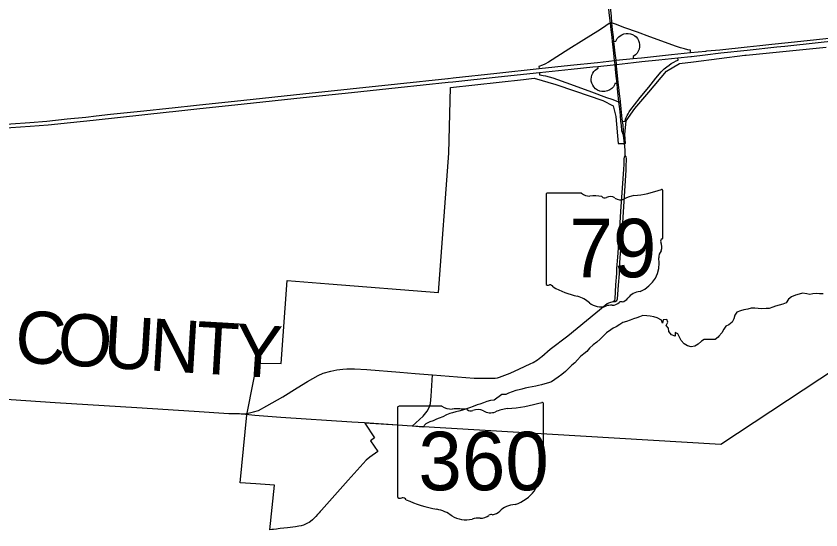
# Model space of a CAD drawing. Extents: x 1853412 to 2125412, y 78841 to 855418.
# Drawn here: x 1962525 to 1977959, y 699538 to 709388 of the extents above; entities that cross this region are included whole.
import ezdxf

# ---------------------------------------------------------------- set-up
doc = ezdxf.new("R2010")
doc.units = 0
for name, color, linetype in [('GM_X_Corporation', 7, 'Continuous'), ('GM_X_County', 7, 'Continuous'), ('GM_X_County_Text', 7, 'Continuous'), ('GM_X_Interstate_Location', 7, 'Continuous'), ('GM_X_Interstate_Route', 7, 'Continuous'), ('GM_X_State_Location', 7, 'Continuous'), ('GM_X_State_Route', 7, 'Continuous'), ('GM_X_State_Shield', 7, 'Continuous'), ('UT_P_Electric', 7, 'Continuous')]:
    doc.layers.add(name, color=color, linetype=linetype)

msp = doc.modelspace()

# ---------------------------------------------------------------- linework, layer by layer
at = {"layer": 'GM_X_Corporation'}
msp.add_lwpolyline([(1978000, 704064), (1977932, 704064), (1977876, 704068), (1977806, 704061), (1977746, 704053), (1977686, 704063), (1977606, 704079), (1977544, 704060), (1977474, 704038), (1977392, 704004), (1977336, 703962), (1977292, 703890), (1977228, 703867), (1977088, 703827), (1977034, 703809), (1976966, 703780), (1976908, 703782), (1976826, 703776), (1976757, 703780), (1976693, 703791), (1976623, 703789), (1976555, 703771), (1976483, 703759), (1976417, 703736), (1976345, 703712), (1976305, 703654), (1976291, 703586), (1976258, 703520), (1976190, 703470), (1976138, 703444), (1976098, 703386), (1976058, 703317), (1976004, 703251), (1975986, 703233), (1975928, 703191), (1975792, 703191), (1975722, 703186), (1975672, 703156), (1975606, 703100), (1975540, 703058), (1975470, 703049), (1975400, 703065), (1975336, 703103), (1975281, 703169), (1975245, 703234), (1975215, 703298), (1975161, 703324), (1975161, 703252), (1975093, 703278), (1975042, 703340), (1975034, 703403), (1974994, 703455), (1975026, 703519), (1975001, 703569), (1974935, 703565), (1974921, 703503), (1974903, 703559), (1974821, 703606), (1974755, 703624), (1974685, 703634), (1974618, 703640), (1974546, 703645), (1974480, 703621), (1974426, 703601), (1974364, 703583), (1974298, 703558), (1974228, 703532), (1974162, 703514), (1974100, 703474), (1974034, 703434), (1973978, 703405), (1973928, 703373), (1973850, 703319), (1973787, 703257), (1973723, 703197), (1973659, 703136), (1973591, 703084), (1973521, 703020), (1973467, 702956), (1973411, 702912), (1973347, 702862), (1973288, 702801), (1973238, 702739), (1973182, 702695), (1973126, 702639), (1973060, 702575), (1972992, 702517), (1972922, 702464), (1972858, 702424), (1972790, 702378), (1972736, 702360), (1972666, 702337), (1972598, 702321), (1972546, 702309), (1972494, 702295), (1972422, 702279), (1972352, 702268), (1972290, 702252), (1972226, 702238), (1972170, 702226), (1972106, 702211), (1972038, 702187), (1971968, 702161), (1971916, 702135), (1971840, 702133), (1971696, 702026), (1971622, 702018), (1971552, 702002), (1971486, 701977), (1971420, 701949), (1971366, 701933), (1971290, 701905), (1971222, 701880), (1971164, 701860), (1971084, 701836), (1971014, 701814), (1970960, 701803), (1970896, 701785), (1970842, 701769), (1970776, 701743), (1970708, 701705), (1970640, 701680), (1970588, 701658), (1970522, 701632), (1970456, 701612), (1970384, 701569), (1970327, 701510), (1970119, 701527), (1969837, 701546), (1969210, 701587), (1969396, 701302), (1969323, 701248), (1969459, 701039), (1969310, 700931), (1969239, 700878), (1968890, 700493), (1968381, 699919), (1968358, 699893), (1968335, 699867), (1968304, 699831), (1968273, 699796), (1968240, 699760), (1968208, 699730), (1968171, 699701), (1968143, 699682), (1968113, 699664), (1968074, 699646), (1968034, 699630), (1967989, 699616), (1967947, 699607), (1967882, 699598), (1967727, 699579), (1967588, 699562), (1967550, 699558), (1967519, 699554), (1967458, 699546), (1967426, 699543), (1967390, 699538), (1967478, 700396), (1967125, 700420), (1966820, 700440), (1966820, 700440), (1966949, 701742), (1967077, 702390), (1967145, 702736), (1967606, 702725), (1967720, 704321), (1968521, 704257), (1970628, 704088), (1970821, 706758), (1970854, 708016), (1972257, 708173), (1972461, 708196), (1972877, 708076), (1973233, 707955), (1973774, 707770), (1973978, 707667), (1974025, 707464), (1974071, 706947), (1974213, 706947), (1974198, 707115), (1974223, 707380), (1974390, 707615), (1974660, 707931), (1974999, 708334), (1975250, 708479), (1975518, 708513), (1976501, 708639), (1976528, 708641), (1978057, 708794)], dxfattribs=at)
at = {"layer": 'GM_X_County'}
msp.add_lwpolyline([(1991425, 702099), (1978895, 703062), (1976042, 701178), (1970119, 701527), (1969837, 701546), (1969206, 701588), (1968963, 701604), (1967601, 701695), (1967104, 701729), (1966807, 701761), (1966648, 701765), (1966605, 701765), (1965937, 701808), (1964838, 701880), (1963273, 701974), (1962141, 702051), (1961404, 702092), (1960067, 702149), (1959325, 702195), (1956245, 702403), (1956176, 702427), (1945541, 702974)], dxfattribs=at)
at = {"layer": 'GM_X_Interstate_Route'}
msp.add_line((1970807, 708193), (1970813, 708194), dxfattribs=at)
at = {"layer": 'GM_X_State_Route'}
msp.add_line((1974196, 706888), (1974170, 707104), dxfattribs=at)
for points in [[(1974208, 706714), (1974207, 706759), (1974204, 706817), (1974196, 706888)], [(1973975, 703918), (1974015, 703918), (1974048, 703933), (1974059, 703967), (1974078, 704230), (1974094, 704448), (1974098, 704538), (1974112, 704759), (1974145, 705203), (1974174, 705637), (1974221, 706435), (1974226, 706482), (1974226, 706542), (1974228, 706604), (1974228, 706652), (1974221, 706691), (1974208, 706714)], [(1973975, 703918), (1974005, 703941), (1974012, 703970), (1974027, 704238), (1974043, 704456), (1974047, 704546), (1974062, 704766), (1974095, 705210), (1974123, 705644), (1974179, 706454), (1974183, 706540), (1974186, 706597), (1974188, 706646), (1974191, 706690), (1974208, 706714)], [(1970512, 702511), (1971311, 702449), (1971712, 702444), (1971758, 702450), (1971793, 702463), (1971997, 702544), (1972181, 702626), (1972380, 702719), (1972439, 702749), (1972523, 702801), (1972585, 702847), (1972604, 702861), (1972768, 703001), (1973106, 703260), (1973820, 703849), (1973863, 703879), (1973908, 703896), (1973975, 703918)], [(1966939, 701770), (1966950, 701771), (1967075, 701800), (1967171, 701829), (1967336, 701916), (1967639, 702088), (1967915, 702263), (1968110, 702386), (1968315, 702499), (1968413, 702541), (1968561, 702582), (1968677, 702608), (1968789, 702621), (1968870, 702628), (1969012, 702626), (1969251, 702614), (1969884, 702562), (1970180, 702537), (1970512, 702511)], [(1970120, 701524), (1970330, 701719), (1970409, 701812), (1970449, 701887), (1970474, 701962), (1970487, 702103), (1970512, 702511)], [(1966839, 701761), (1966880, 701764), (1966939, 701770)]]:
    msp.add_lwpolyline(points, dxfattribs=at)
at = {"layer": 'GM_X_State_Shield'}
for p, q in [((1972688, 705962), (1972688, 704261)), ((1973367, 705991), (1972710, 705991)), ((1974930, 705143), (1974930, 706033)), ((1974930, 705144), (1974930, 705143)), ((1972642, 701061), (1972642, 701951)), ((1969841, 701880), (1969841, 700178)), ((1970689, 701909), (1969868, 701909)), ((1972642, 701061), (1972642, 701061))]:
    msp.add_line(p, q, dxfattribs=at)
for centre, radius, start, end in [((1972714, 705966), 26, 98.1301, 188.1301), ((1973523, 706189), 252, 231.6195, 271.1119), ((1974131, 708311), 2377, 275.8445, 288.9065), ((1974905, 706037), 25, 351.8621, 97.738), ((1973607, 705036), 904, 80.4867, 94.9883), ((1973812, 705974), 72.7, 219.7921, 297.1024), ((1973919, 705778), 151, 54.4667, 119.1411), ((1974114, 706047), 182, 233.8562, 294.8282), ((1974435, 705472), 478, 97.3462, 120.7689), ((1974924, 705078), 38.6, 107.944, 210.337), ((1974678, 704966), 232, 340.033, 23.6496), ((1974903, 705140), 26.7, 289.6038, 7.7341), ((1975019, 704771), 169, 136.8065, 186.9296), ((1974265, 704658), 595, 292.3089, 8.9858), ((1972714, 704257), 26.2, 171.9584, 258.3066), ((1972718, 704431), 200, 267.339, 280.6039), ((1972759, 704163), 72.1, 29.7484, 93.2717), ((1973669, 705691), 1716, 240.4129, 257.1985), ((1974515, 703783), 326, 94.4031, 142.5768), ((1973158, 703496), 537, 47.1842, 75.836), ((1974103, 704096), 192, 282.8732, 323.2771), ((1973738, 704154), 341, 230.7004, 286.2918), ((1973935, 703566), 280, 85.6951, 111.2099), ((1973960, 704027), 182, 268.777, 315.5493), ((1974124, 703862), 51.1, 65.7517, 132.6484)]:
    msp.add_arc(centre, radius, start, end, dxfattribs=at)
for centre, major_axis, start_param, end_param in [((1971644, 704228), (2971, 0), 4.814394, 5.042369), ((1972611, 701955), (31.2, 0), 6.141152, 7.989035), ((1969873, 701883), (32.5, 0), 1.712693, 3.28349), ((1970884, 702106), (315, 0), 4.042523, 4.731795), ((1970988, 700954), (1130, 0), 1.404758, 1.657858), ((1971245, 701892), (90.8, 0), 3.836095, 5.185415), ((1971378, 701695), (189, 0), 0.950623, 2.079405), ((1971622, 701965), (227, 0), 4.081561, 5.145723), ((1972023, 701389), (598, 0), 1.699011, 2.107814), ((1972635, 700996), (48.3, 0), 1.883978, 3.671073), ((1972609, 701058), (33.4, 0), 5.05454, 6.418171), ((1972328, 700883), (290, 0), 5.934695, 6.695948), ((1972754, 700689), (211, 0), 2.387724, 3.262537), ((1971811, 700575), (743, 0), 5.101752, 6.440018), ((1969873, 700175), (32.7, 0), 3.00124, 4.508301), ((1969878, 700349), (250, 0), 4.665946, 4.897461), ((1969929, 700080), (90.1, 0), 0.519207, 1.627899), ((1971067, 701609), (2146, 0), 4.195997, 4.488961), ((1970427, 699414), (671, 0), 0.823519, 1.323587), ((1972124, 699701), (407, 0), 1.647645, 2.488434), ((1971153, 700072), (426, 0), 4.026481, 4.996735), ((1971430, 699944), (227, 0), 4.691044, 5.507374), ((1971636, 699780), (63.9, 0), 1.147584, 2.315152), ((1971608, 700014), (240, 0), 4.937069, 5.64225), ((1971399, 699484), (350, 0), 1.495662, 1.94098)]:
    msp.add_ellipse(centre, major_axis=major_axis, ratio=0.8, start_param=start_param, end_param=end_param, dxfattribs=at)
at = {"layer": 'UT_P_Electric'}
for p, q in [((1975477, 708616), (1975739, 708648)), ((1974156, 707369), (1974143, 707475))]:
    msp.add_line(p, q, dxfattribs=at)
for points in [[(1973924, 709254), (1973907, 709402), (1973894, 709523), (1973880, 709660)], [(1974042, 708427), (1974039, 708460), (1974030, 708542), (1974015, 708680), (1973996, 708852), (1973990, 708899), (1973981, 708987), (1973965, 709125), (1973952, 709257), (1973940, 709387), (1973928, 709501), (1973922, 709555)], [(1973952, 709257), (1973924, 709254), (1973897, 709244), (1973837, 709202), (1973809, 709181), (1973683, 709100), (1973412, 708930), (1973124, 708751), (1972734, 708507), (1972665, 708469), (1972617, 708445), (1972550, 708421), (1972554, 708380)], [(1974124, 707366), (1974113, 707479), (1974101, 707607), (1974085, 707744), (1974071, 707869), (1974059, 707992), (1974050, 708097), (1974033, 708236), (1974019, 708369), (1974012, 708457), (1974002, 708539), (1973987, 708678), (1973968, 708850), (1973963, 708897), (1973954, 708985), (1973938, 709123), (1973924, 709254)], [(1975460, 708687), (1975455, 708735), (1975406, 708743), (1975346, 708757), (1975267, 708779), (1975169, 708814), (1974908, 708908), (1974678, 708993), (1974441, 709080), (1974200, 709164), (1974021, 709230), (1973965, 709253), (1973952, 709257)], [(1973990, 708899), (1974026, 708904), (1974037, 708930), (1974054, 708957), (1974081, 708987), (1974109, 709011), (1974142, 709031), (1974180, 709047), (1974223, 709056), (1974264, 709056), (1974306, 709048), (1974344, 709035), (1974388, 709009), (1974413, 708988), (1974439, 708957), (1974460, 708923), (1974472, 708884), (1974480, 708844), (1974482, 708798), (1974474, 708756), (1974457, 708713), (1974434, 708677), (1974405, 708644), (1974357, 708612), (1974361, 708573)], [(1977266, 708814), (1977909, 708884), (1978729, 708968), (1979319, 709027), (1979773, 709055), (1980339, 709065), (1980848, 709048), (1981728, 708986), (1982178, 708950), (1982699, 708912)], [(1975773, 708720), (1976021, 708741), (1976547, 708798), (1976787, 708821), (1977020, 708847), (1977333, 708880), (1977873, 708936), (1978652, 709022)], [(1975739, 708648), (1976038, 708684), (1976544, 708737), (1977114, 708798), (1977266, 708814)], [(1970813, 708194), (1970909, 708204), (1971746, 708293), (1972554, 708380), (1973159, 708446), (1973674, 708498), (1974002, 708539), (1974030, 708542), (1974361, 708573), (1974518, 708589)], [(1974156, 707369), (1974203, 707373), (1974213, 707413), (1974225, 707443), (1974241, 707479), (1974260, 707514), (1974282, 707551), (1974315, 707598), (1974385, 707686), (1974495, 707824), (1974657, 708025), (1974796, 708199), (1974897, 708321), (1974953, 708378), (1975002, 708418), (1975046, 708449), (1975089, 708478), (1975139, 708505), (1975183, 708527), (1975220, 708540), (1975213, 708588)], [(1974518, 708589), (1975095, 708650), (1975460, 708687)], [(1974522, 708515), (1974848, 708550), (1975213, 708588)], [(1975213, 708588), (1975467, 708615), (1975477, 708616)], [(1975460, 708687), (1975752, 708718), (1975773, 708720)], [(1974050, 708097), (1974010, 708094), (1974000, 708069), (1973979, 708034), (1973949, 708002), (1973908, 707972), (1973864, 707953), (1973815, 707942), (1973760, 707941), (1973716, 707951), (1973676, 707969), (1973639, 707995), (1973607, 708029), (1973583, 708064), (1973566, 708102), (1973556, 708143), (1973554, 708181), (1973557, 708218), (1973567, 708254), (1973582, 708293), (1973603, 708326), (1973630, 708352), (1973657, 708373), (1973686, 708390), (1973683, 708423)], [(1973585, 708413), (1973683, 708423), (1973977, 708453)], [(1973977, 708453), (1974012, 708457), (1974039, 708460), (1974368, 708499), (1974522, 708515)], [(1974143, 707475), (1974143, 707481), (1974131, 707608), (1974115, 707744), (1974114, 707759), (1974096, 707895), (1974084, 708018), (1974072, 708124), (1974047, 708372), (1974042, 708427)], [(1970813, 708120), (1970898, 708129), (1971771, 708222), (1972561, 708309), (1973167, 708371), (1973585, 708413)], [(1972561, 708309), (1972564, 708263), (1972598, 708258), (1972634, 708251), (1972680, 708243), (1972749, 708224), (1972815, 708203), (1973155, 708081), (1973562, 707933), (1973846, 707830), (1973948, 707792), (1973998, 707775), (1974044, 707755), (1974085, 707744), (1974115, 707744)], [(1965516, 707629), (1965983, 707680), (1966891, 707776), (1968021, 707899), (1968930, 707994), (1969841, 708092), (1970807, 708193)], [(1965528, 707559), (1965990, 707609), (1966898, 707706), (1968030, 707824), (1968956, 707923), (1969852, 708019), (1970813, 708120)], [(1960174, 707397), (1960547, 707376), (1961032, 707348), (1961350, 707329), (1961637, 707317), (1961917, 707313), (1962173, 707316), (1962427, 707324), (1962785, 707346), (1963112, 707374), (1963506, 707415), (1963862, 707453), (1964060, 707477), (1964337, 707505), (1964973, 707574), (1965452, 707622), (1965516, 707629)], [(1960186, 707322), (1961351, 707256), (1961611, 707245), (1961920, 707240), (1962425, 707251), (1962792, 707275), (1963138, 707304), (1963565, 707347), (1964001, 707394), (1965459, 707551), (1965528, 707559)], [(1974170, 707104), (1974143, 707185), (1974132, 707299), (1974124, 707366)], [(1974170, 707104), (1974175, 707187), (1974164, 707301), (1974156, 707369)]]:
    msp.add_lwpolyline(points, dxfattribs=at)

# ---------------------------------------------------------------- texts
at = {"layer": 'GM_X_County_Text'}
for s, rotation, p in [('C', 356.5016, (1962486, 702754)), ('O', 356.5016, (1963299, 702705)), ('U', 356.5021, (1964181, 702651)), ('N', 356.5129, (1965064, 702597)), ('T', 356.6958, (1965951, 702543)), ('Y', 356.1453, (1966695, 702500))]:
    msp.add_text(s, height=1000, rotation=rotation, dxfattribs=at).set_placement(p)
at = {"layer": 'GM_X_Interstate_Location'}
for s in ['.', '-', ',']:
    msp.add_text(s, height=1, dxfattribs=at).set_placement((1970239, 708136))
msp.add_text('70', height=1, rotation=0, dxfattribs=at).set_placement((1970034, 707929))
at = {"layer": 'GM_X_State_Location'}
for s in ['s', 'r']:
    msp.add_text(s, height=1, dxfattribs=at).set_placement((1968187, 699659))
msp.add_text('360', height=1, rotation=0, dxfattribs=at).set_placement((1967834, 699586))
at = {"layer": 'GM_X_State_Shield'}
for s, p in [('79', (1973136, 704381)), ('360', (1970240, 700298))]:
    msp.add_text(s, height=1120.7, dxfattribs=at).set_placement(p)

doc.saveas('drawing.dxf')
